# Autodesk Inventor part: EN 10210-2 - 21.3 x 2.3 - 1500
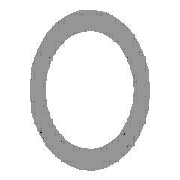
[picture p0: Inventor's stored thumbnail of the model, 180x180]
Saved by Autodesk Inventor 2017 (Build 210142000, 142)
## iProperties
Created: 2017-11
Part Number: EN 10210-2 - 21.3 x 2.3 - 1500
Material: Steel, Mild
Description: Pipe
Document SubType Name: Modeling
Standard: DIN
Designer: iusti
Standard Revision: 2006-07
Standards Organization: DIN
Language: en-US
Size Designation: 21.3 x 2.3
Categories: <MemberInstance><Categories><Category DisplayName="Structural Shapes" InternalName="089c4875-fa83-4c05-b084-43b9cc11f5ed" Mnemonic="GRDR"><CategoryParameter Dis
Stock Number: 21.3 x 2.3
Density: 7.85 g/cm^3
Appearance: Semi-Polished
IsCustomPart: 1
G_L: 1500.000 mm
G_W: 21.300 mm
G_H: 21.300 mm
_CCFamilyMember: 1
_CCFamilyDisplayName: DIN EN 10210-2 - Pipe
_FrameMemberDoc: Frame Member File
_Version: 15.0.0
_GetPNFromCC: 1
Author: iusti
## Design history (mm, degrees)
node "Start plane"
node "End plane"
sketch "Sketch"
  geometry: C1 r 8.35 at (0, 0); C2 r 10.65 at (0, 0); 2 further points
  constraints: 3 coincident, 2 centre point
  dimensions: "d0" = 21.3 diameter of C2 (= G_H); "d1" = 2.3 radial gap between concentric circles of C2 C1 (= G_T)
extrude "Body" new body sketch "Sketch" stored distance "d2" = 1500 (= G_L); taper "d3" = 0 deg
node "Driven Length"
  sketch "Sketch3"
    geometry: L1 (0, 0)-(10, 0) reference
    constraints: 2 end point, 1 horizontal
  workplane "Work Plane3"
  sketch "Sketch4"
    geometry: L1 (-2, 0)-(12, 0) reference; L2 (-2, 1500)-(12, 1500) reference
    dimensions: "d7" = 1500 distance between parallel lines of L1 L2 (derived)
body "Solid1"
other parameters: "G_H" = 21.3 [user parameter; used in 1 equation term], "G_T" = 2.3 [user parameter; used in 1 equation term], "G_L" = 1500 (= d7) [user parameter; used in 1 equation term], "G_OFFSET_START" = 0 [user parameter; used in 1 equation term], "G_OFFSET_END" = 0 [user parameter; used in 1 equation term], "d4" = 0 (computed from G_OFFSET_START), "d6" = 90 deg
